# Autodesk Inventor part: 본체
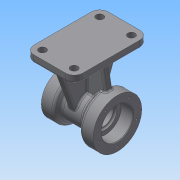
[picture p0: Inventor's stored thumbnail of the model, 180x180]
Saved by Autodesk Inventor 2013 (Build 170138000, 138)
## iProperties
Created: 2015-08
Part Number: 본체
Material: 일반
Document SubType Name: Modeling
Designer: Administrator
Density: 1 g/cm^3
Author: Administrator
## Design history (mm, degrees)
sketch "스케치1"
  geometry: L1 (0, 0)-(90, 0); L2 (90, 26)-(90, 40); L3 (90, 40)-(70, 40); L4 (58.253, 26)-(25.196, 26); L5 (25.196, 26)-(20, 35); L6 (20, 35)-(0, 35); L7 (0, 35)-(0, 20); L8 (70, 40)-(58.253, 26); L9 (70, 40)-(86.853, 40); L10 (16.841, 19)-(16.841, 19); L11 (45, 0)-(45, 68.509); L12 (0, 20)-(17, 20); L13 (17, 20)-(17, 16); L14 (90, 26)-(70, 26); L15 (70, 26)-(70, 19); L16 (70, 19)-(70, 19); L17 (67, 16)-(67, 16); L18 (67, 16)-(17, 16); A1 r 3 centre (70, 16) between (70, 19) and (67, 16); 3 further points; 1 other entity
  constraints: 36 end point, 8 perpendicular, 4 parallel, 2 horizontal, 2 point on circle, 2 point on line, 2 tangent, 1 centre point, 1 coincident, 1 midpoint, 2 other
  dimensions: "d0" = 90 distance of L1.start L1.end; "d1" = 80 diameter of L3 L1; "d2" = 20 distance of L2.end L3.end; "d3" = 52 diameter of L4 L1; "d5" = 20 distance of L5.end L6.end; "d6" = 70 diameter of L6 L1; "d7" = 60 deg angle of L4 L5; "d8" = 130 deg angle of L8 L9; "d69" = 40 diameter of L12 L1; "d75" = 20 distance of L2.start L14.end; "d76" = 52 diameter of L14 L1; "d77" = 3 distance of L15.end point (67, 19); "d78" = 3 distance of point (67, 19) L17.end; "d79" = 32 diameter of L18 L1; "d80" = 17 distance of L7.end L12.end; "d81" = 3 radius of A1
revolve "회전1" sketch "스케치1" stored, may be unused: angle "d15" = 90 deg
fillet "모깎기1" dims "d16" = 5
sketch "스케치2"
  geometry: L1 (-90, 26)-(-90, 40) reference; L2 (-90, 40)-(-72.332, 40) reference; L3 (-68.501, 38.214)-(-59.751, 27.786) reference; L4 (-55.921, 26)-(-28.083, 26) reference; L5 (-23.753, 28.5)-(-21.443, 32.5) reference; L6 (-17.113, 35)-(0, 35) reference; L7 (0, 35)-(0, 20) reference; L8 (0, -20)-(0, -35) reference; L9 (0, -35)-(-17.113, -35) reference; L10 (-21.443, -32.5)-(-23.753, -28.5) reference; L11 (-28.083, -26)-(-55.921, -26) reference; L12 (-59.751, -27.786)-(-68.501, -38.214) reference; L13 (-72.332, -40)-(-90, -40) reference; L14 (-90, -40)-(-90, -26) reference; L15 (0, 78)-(-80, 78); L16 (-80, 78)-(-80, 90); L17 (-80, 90)-(0, 90); L18 (0, 90)-(0, 78); L19 (-70, 26)-(-90, 26) reference; L20 (0, 20)-(-17, 20) reference; L21 (-17, 20)-(-17, 16) reference; L22 (-17, 16)-(-67, 16) reference; L23 (-70, 19)-(-70, 26) reference; L24 (-90, -26)-(-70, -26) reference; L25 (-70, -26)-(-70, -19) reference; L26 (-67, -16)-(-17, -16) reference; L27 (-17, -16)-(-17, -20) reference; L28 (-17, -20)-(0, -20) reference; A1 r 5 centre (-72.332, 35) between (-68.501, 38.214) and (-72.332, 40) reference; A2 r 5 centre (-55.921, 31) between (-59.751, 27.786) and (-55.921, 26) reference; A3 r 5 centre (-28.083, 31) between (-28.083, 26) and (-23.753, 28.5) reference; A4 r 5 centre (-17.113, 30) between (-17.113, 35) and (-21.443, 32.5) reference; A5 r 5 centre (-17.113, -30) between (-21.443, -32.5) and (-17.113, -35) reference; A6 r 5 centre (-28.083, -31) between (-23.753, -28.5) and (-28.083, -26) reference; A7 r 5 centre (-55.921, -31) between (-55.921, -26) and (-59.751, -27.786) reference; A8 r 5 centre (-72.332, -35) between (-72.332, -40) and (-68.501, -38.214) reference; A9 r 3 centre (-70, 16) between (-67, 16) and (-70, 19) reference; A10 r 3 centre (-70, -16) between (-70, -19) and (-67, -16) reference; 1 further point
  constraints: 8 end point, 3 perpendicular, 1 parallel
  dimensions: "d17" = 12 distance of L15.end L16.end; "d19" = 90 distance from line of L17 point (0, 0); "d20" = 80 distance of L16.end L17.end
extrude "돌출1" join sketch "스케치2" stored distance "d21" = 122; taper "d22" = 0 deg
sketch "스케치3"
  geometry: L1 (-90, 26)-(-90, 40) reference; L2 (-90, 40)-(-72.332, 40) reference; L3 (-68.501, 38.214)-(-59.751, 27.786) reference; L4 (-55.921, 26)-(-28.083, 26) reference; L5 (-23.753, 28.5)-(-21.443, 32.5) reference; L6 (-17.113, 35)-(0, 35) reference; L7 (0, 35)-(0, 20) reference; L8 (0, -20)-(0, -35) reference; L9 (0, -35)-(-17.113, -35) reference; L10 (-21.443, -32.5)-(-23.753, -28.5) reference; L11 (-28.083, -26)-(-55.921, -26) reference; L12 (-59.751, -27.786)-(-68.501, -38.214) reference; L13 (-72.332, -40)-(-90, -40) reference; L14 (-90, -40)-(-90, -26) reference; L15 (-80, 78)-(-80, 90) reference; L16 (-80, 90)-(0, 90) reference; L17 (0, 90)-(0, 78) reference; L18 (0, 78)-(-80, 78) reference; L19 (-6.839, 78)-(-6.839, 28.5); L20 (-80, 78)-(-70, 78); L21 (-70, 78)-(-78.728, 28.5); L22 (-6.839, 28.5)-(-19.841, 28.5); L23 (-19.841, 28.5)-(-19.841, 23.373); L24 (-19.841, 23.373)-(-68.664, 23.373); L25 (-72.332, 28.5)-(-78.728, 28.5); L26 (-70, 26)-(-90, 26) reference; L27 (0, 20)-(-17, 20) reference; L28 (-17, 20)-(-17, 16) reference; L29 (-17, 16)-(-67, 16) reference; L30 (-70, 19)-(-70, 26) reference; L31 (-90, -26)-(-70, -26) reference; L32 (-70, -26)-(-70, -19) reference; L33 (-67, -16)-(-17, -16) reference; L34 (-17, -16)-(-17, -20) reference; L35 (-17, -20)-(0, -20) reference; L36 (-72.332, 28.5)-(-68.664, 28.5); L37 (-68.664, 28.5)-(-68.664, 23.373); A1 r 5 centre (-72.332, 35) between (-68.501, 38.214) and (-72.332, 40) reference; A2 r 5 centre (-55.921, 31) between (-59.751, 27.786) and (-55.921, 26) reference; A3 r 5 centre (-28.083, 31) between (-28.083, 26) and (-23.753, 28.5) reference; A4 r 5 centre (-17.113, 30) between (-17.113, 35) and (-21.443, 32.5) reference; A5 r 5 centre (-17.113, -30) between (-21.443, -32.5) and (-17.113, -35) reference; A6 r 5 centre (-28.083, -31) between (-23.753, -28.5) and (-28.083, -26) reference; A7 r 5 centre (-55.921, -31) between (-55.921, -26) and (-59.751, -27.786) reference; A8 r 5 centre (-72.332, -35) between (-72.332, -40) and (-68.501, -38.214) reference; A9 r 3 centre (-70, 16) between (-67, 16) and (-70, 19) reference; A10 r 3 centre (-70, -16) between (-70, -19) and (-67, -16) reference; 2 further points
  constraints: 18 end point, 3 parallel, 3 perpendicular, 3 point on line, 1 collinear
  dimensions: "d24" = 10 distance of L15.start L20.end; "d25" = 80 deg angle of L20 L21; "d26" = 6.83866 distance between parallel lines of L19 L17
extrude "돌출2" join sketch "스케치3" stored distance "d27" = 12; taper "d28" = 0 deg
node "작업 평면1"
sketch "스케치4"
  geometry: L1 (-61, 78)-(-61, 90) reference; L2 (-61, 90)-(61, 90) reference; L3 (61, 90)-(61, 78) reference; L4 (61, 78)-(6, 78) reference; L5 (6, 78)-(6, 25.298) reference; L6 (-6, 25.298)-(-6, 78) reference; L7 (-6, 78)-(-61, 78) reference; L8 (51, 78)-(23.108, 1.368); L9 (-56.799, 78)-(-51, 78); L10 (-51, 78)-(-23.108, 1.368); L11 (51, 78)-(-51, 78); L12 (23.108, 1.368)-(-23.108, 1.368); C1 r 16 at (0, 0) reference; A1 r 26 centre (0, 0) between (-6, 25.298) and (6, 25.298) reference; 2 further points
  constraints: 10 end point, 3 point on line, 1 coincident, 1 parallel
  dimensions: "d30" = 10 distance of L3.end L8.start; "d33" = 110 deg angle of L9 L10; "d82" = 10 distance from line of L1 point (-51, 78); "d83" = 70 deg angle of L11 L8
extrude "돌출3" join sketch "스케치4" stored distance "d34" = 12; taper "d35" = 0 deg
fillet "모깎기2" dims "d36" = 14
sketch "스케치5"
  geometry: C1 r 6 at (0, 108); A1 r 14 centre (0, 108) between (0, 122) and (-14, 108) reference; 1 further point
  constraints: 1 centre point, 1 coincident
  dimensions: "d37" = 12 diameter of C1
extrude "돌출4" cut sketch "스케치5" distance "d38" = 12; taper "d39" = 0 deg
sketch "스케치6"
  geometry: L1 (-78, 6)-(-78, 51) reference; L2 (-90, 61)-(-78, 61) reference; L3 (-78, 6)-(-25.298, 6) reference; L4 (-78, 51)-(-78, 6) reference; L5 (-78, 51)-(-6.815, 25.091) reference; L6 (-6.815, -25.091)-(-78, -51) reference; L7 (-78, -51)-(-78, -61) reference; L8 (-78, -61)-(-90, -61) reference; L9 (-90, -61)-(-90, 61) reference; L10 (-90, 61)-(-78, 61) reference; L11 (-78, 61)-(-78, 51) reference; L12 (-25.298, -6)-(-78, -6) reference; L13 (-78, -6)-(-78, -51) reference; L14 (-54, 18)-(-60, 18); L15 (-54, 30)-(-60, 30); L16 (-1.368, 15.941)-(-1.368, -15.941) reference; A1 r 6 centre (-54, 24) between (-54, 18) and (-54, 30); A2 r 6 centre (-60, 24) between (-60, 30) and (-60, 18); A3 r 16 centre (0, 0) between (-1.368, -15.941) and (-1.368, 15.941) reference; A4 r 26 centre (0, 0) between (-6.815, -25.091) and (-6.815, 25.091) reference; A5 r 26 centre (0, 0) between (-25.298, -6) and (-6.815, -25.091) reference; A6 r 26 centre (0, 0) between (-6.815, 25.091) and (-25.298, 6) reference; A7 r 16 centre (0, 0) between (-1.368, 15.941) and (-1.368, -15.941) reference; 3 further points
  constraints: 6 point on circle, 4 end point, 2 centre point, 2 coincident, 2 point on line, 2 tangent, 1 other
  dimensions: "d46" = 18 distance from line of L1 point (-60, 24); "d47" = 24 distance from line of L1 point (-54, 24); "d49" = 24 distance of point (-60, 0) point (-60, 24); "d50" = 24 vertical distance of point (-60, 0) point (-54, 24); "d51" = 12 diameter of A1; "d52" = 12 diameter of A2
extrude "돌출5" cut sketch "스케치6" distance "d53" = 12; taper "d54" = 0 deg
sketch "스케치7"
  geometry: C1 r 26 at (0, 0) reference; 1 further point
  dimensions: "d58" = 33 distance of C1.centre point (33, 0)
hole "구멍1" sketch "스케치7" at (33, 0) diameter "d59" = 3.242; stored, may be unused: countersink angle "d63" = 90 deg, drill point angle "d65" = 118 deg; dims "d60" = 10, "d61" = 4, "d62" = 2, "d64" = 13
sketch "스케치8"
  geometry: L1 (-90, -51.472)-(-78, -51.472) reference; L2 (-78, -51.472)-(-78, -60.416) reference; L3 (-78, -60.416)-(-90, -60.416) reference; L4 (-90, -60.416)-(-90, -51.472) reference; L5 (-90, 42.528)-(-78, 42.528) reference; L6 (-78, 42.528)-(-78, 6) reference; L7 (-78, 6)-(-78, -6) reference; L8 (-78, -6)-(-78, -42.528) reference; L9 (-78, -42.528)-(-90, -42.528) reference; L10 (-90, -42.528)-(-90, 42.528) reference; L11 (-78, 6)-(-38.964, 6) reference; L12 (-38.964, -6)-(-78, -6) reference; L13 (-90, 60.416)-(-78, 60.416) reference; L14 (-78, 60.416)-(-78, 51.472) reference; L15 (-78, 51.472)-(-90, 51.472) reference; L16 (-90, 51.472)-(-90, 60.416) reference; C1 r 26 at (0, 0) reference; C2 r 19 at (0, 0) reference; C3 r 16 at (0, 0) reference; C4 r 16 at (0, 0); A1 r 39.423 centre (0, 0) between (-38.964, -6) and (-38.964, 6) reference
  constraints: 1 centre point, 1 coincident, 1 concentric
extrude "돌출6" cut sketch "스케치8" stored distance "d84" = 12; taper "d85" = 0 deg
sketch "스케치9"
  geometry: C1 r 35 at (0, 0) reference; 1 further point
  dimensions: "d89" = 27 distance of C1.centre point (-27, 0)
hole "구멍2" sketch "스케치9" at (-27, 0) diameter "d90" = 3.242; stored, may be unused: countersink angle "d94" = 90 deg, drill point angle "d96" = 118 deg; dims "d91" = 10, "d92" = 4, "d93" = 2, "d95" = 13
fillet "모깎기3" dims "d100" = 0.3
chamfer "모따기1" distance "d101" = 1; stored, may be unused: second distance "d102" = 2, angle "d103" = 45 deg
fillet "모깎기4" dims "d104" = 3
fillet "모깎기5" dims "d105" = 3
fillet "모깎기6" dims "d106" = 3
fillet "모깎기7" dims "d107" = 3
node "솔리드1"
pattern_linear "직사각형 패턴1" dims "d42" = 52, "d45" = 94
pattern_linear "직사각형 패턴2" dims "d57" = 48
pattern_circular "원형 패턴2" dims angle "d87" = 360 deg
pattern_circular "원형 패턴3" dims angle "d98" = 360 deg
node "절단 모서리 투영1"
node "절단 모서리 투영2"
node "절단 모서리 투영3"
node "절단 모서리 투영4"
node "절단 모서리 투영5"
